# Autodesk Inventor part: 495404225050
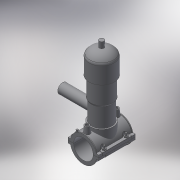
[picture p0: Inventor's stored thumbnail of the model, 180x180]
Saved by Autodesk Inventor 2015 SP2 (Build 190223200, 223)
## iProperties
Created: 2017-07
Part Number: 495404225050
Material: Generic
Description: PLASSON TAPPING VALVE 225-50
Document SubType Name: Modeling
Designer: KIM
Density: 1 g/cm^3
Appearance: Default
Author: KIM
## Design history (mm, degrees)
derived "495404-4954S4.ipt"
feature "Solid1::495404-4954S4.ipt"
feature "Solid2::495404-4954S4.ipt"
tag "TaggingFeature1"
body "Solid1"
body "Solid2"
other parameters: "d0" = 225, "d2" = 295.1, "d3" = 56.25, "d4" = 176, "d5" = 0, "d6" = 0.1, "d8" = 0, "d19" = 6, "d20" = 6, "d21" = 105.6, "d23" = 0, "d24" = 52.8, "d26" = 0, "d27" = 3, "d28" = 3, "d29" = 3, "d30" = 75, "d31" = 6, "d32" = 0, "d33" = 0, "d34" = 0.6, "d40" = 136.89, "d47" = 182.625, "d70" = 15, "d72" = 0, "d73" = 6, "d75" = 5, "d76" = 0, "d77" = 11.25, "d78" = 142.5, "d79" = 15, "d80" = 70.4, "d82" = 5 deg, "d84" = 4, "d85" = 14, "d86" = 0, "d87" = 3, "d88" = 0, "d89" = 1, "d90" = 1, "d91" = 140.8, "d92" = 0, "d93" = 0.5, "d94" = 118.42105, "d96" = 271.1475, "d97" = 3.52, "d98" = 0, "d120" = 140 deg, "d121" = 24.228, "d122" = 20 deg, "d123" = 526.5, "d124" = 157.95, "d126" = 0, "d143" = 231.75, "d145" = 29.42308, "d149" = 3.375, "d150" = 32.36538, "d153" = 176, "d154" = 0, "d156" = 131.625, "d157" = 160 deg, "d159" = 7.65, "d161" = 3.375, "d162" = 105.6, "d163" = 0, "d164" = 112.5, "d167" = 22.5, "d168" = 128.41463, "d170" = 3.375, "d172" = 0, "d173" = 1, "d175" = 112.5, "d176" = 20 deg, "d177" = 15.75, "d178" = 38.25, "d180" = 0, "d183" = 15.3, "d184" = 12.6, "d185" = 57.2, "d186" = 57.2, "d187" = 131.625, "d188" = 11.475, "d189" = 15.75, "d190" = 0, "d191" = 197.4375, "d193" = 7.65, "d194" = 4.4, "d195" = 90 deg, "d197" = 0, "d199" = 0, "d205" = 14.64, "d206" = 81.33333, "d207" = 244, "d208" = 224.48, "d209" = 207.4, "d210" = 200.08, "d211" = 146.4, "d212" = 85.4, "d213" = 65.88, "d214" = 73.2, "d216" = 21.96, "d217" = 70.76, "d218" = 80.52, "d220" = 225, "d222" = 0, "d223" = 263.25, "d224" = 152, "d225" = 51, "d229" = 152, "d230" = 0, "d_" = 225, "B_" = 227, "H_" = 152, "L_" = 176, "d_t" = 6, "H_1" = 51, "H_2" = 244, "d148" = 3.375, "d160" = 3.375, "d169" = 3.375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
